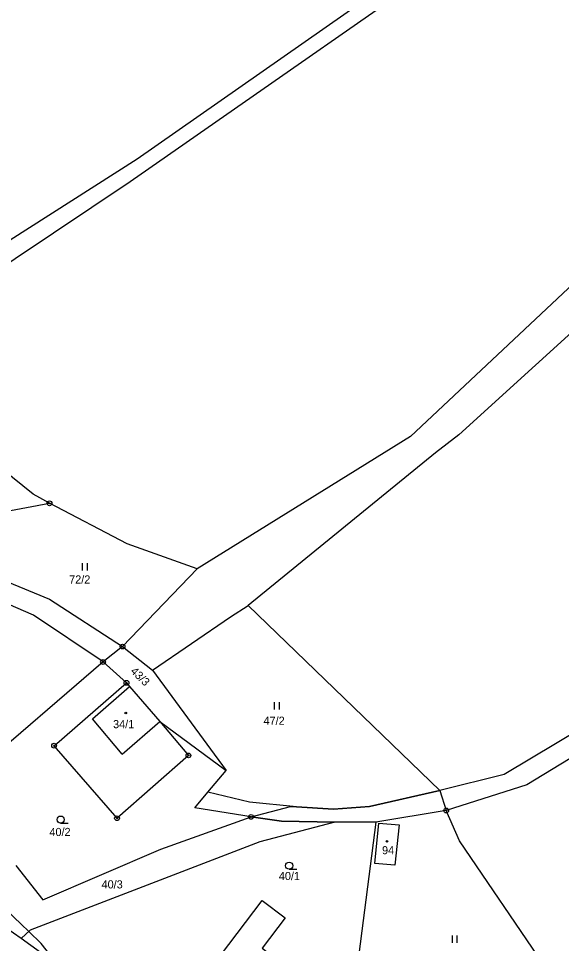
# Model space of a CAD drawing. Extents: x -547623 to -538651, y -1096714 to -1086522.
# Drawn here: x -544383.3 to -544269.6, y -1093367 to -1093173.4 of the extents above; entities that cross this region are included whole.
import ezdxf

# ---------------------------------------------------------------- set-up
doc = ezdxf.new("R2010")
doc.units = 0
for name, color, linetype in [('Vrstva 1', 7, 'Continuous'), ('Vrstva 25', 7, 'Continuous'), ('Vrstva 30', 7, 'Continuous'), ('Vrstva 33', 7, 'Continuous'), ('Vrstva 52', 7, 'Continuous'), ('Vrstva 83', 7, 'Continuous'), ('Vrstva 86', 7, 'Continuous'), ('Vrstva 90', 7, 'Continuous'), ('Vrstva 92', 7, 'Continuous')]:
    doc.layers.add(name, color=color, linetype=linetype)

msp = doc.modelspace()

# ---------------------------------------------------------------- linework, layer by layer
at = {"layer": 'Vrstva 1'}
msp.add_line((-544270.28, -1093375.95), (-544290.96, -1093345.5), dxfattribs=at)
for points in [[(-544280.03, -1093147.98), (-544358.44, -1093202.82)], [(-544278.8, -1093150.99), (-544359.87, -1093207.54)], [(-544358.44, -1093202.82), (-544394.72, -1093225.91)], [(-544359.87, -1093207.54), (-544408.12, -1093239.81)], [(-544264.85, -1093226.71), (-544301.27, -1093260.9)], [(-544259.07, -1093231.36), (-544291.12, -1093260.53)], [(-544301.27, -1093260.9), (-544345.86, -1093288.56)], [(-544291.12, -1093260.53), (-544296.03, -1093264.31)], [(-544380.17, -1093272.94), (-544393.6, -1093262.19)], [(-544296.03, -1093264.31), (-544335.21, -1093296.26)], [(-544376.78, -1093274.85), (-544380.17, -1093272.94)], [(-544399.42, -1093279.07), (-544376.78, -1093274.85)], [(-544360.55, -1093283.34), (-544376.78, -1093274.85)], [(-544402.54, -1093284.32), (-544376.8, -1093294.93)], [(-544345.86, -1093288.56), (-544360.55, -1093283.34)], [(-544380.12, -1093298.26), (-544403.14, -1093288.28)], [(-544345.86, -1093288.56), (-544361.49, -1093304.84)], [(-544376.8, -1093294.93), (-544361.49, -1093304.84)], [(-544338.9, -1093298.62), (-544335.21, -1093296.26)], [(-544295.12, -1093334.97), (-544335.21, -1093296.26)], [(-544365.57, -1093308.07), (-544380.12, -1093298.26)], [(-544355.21, -1093309.78), (-544338.9, -1093298.62)], [(-544361.49, -1093304.84), (-544365.57, -1093308.07)], [(-544361.49, -1093304.84), (-544355.21, -1093309.78)], [(-544365.57, -1093308.07), (-544392.44, -1093331.18)], [(-544360.66, -1093312.44), (-544365.57, -1093308.07)], [(-544355.21, -1093309.78), (-544339.84, -1093330.78)], [(-544375.82, -1093325.59), (-544360.66, -1093312.44)], [(-544360.66, -1093312.44), (-544360.03, -1093313.18)], [(-544360.03, -1093313.18), (-544353.7, -1093320.51)], [(-544253.71, -1093314.94), (-544281.65, -1093331.64)], [(-544353.7, -1093320.51), (-544347.71, -1093327.63)], [(-544353.7, -1093320.51), (-544339.84, -1093330.78)], [(-544257.53, -1093322.02), (-544276.92, -1093333.82)], [(-544362.64, -1093340.78), (-544375.82, -1093325.59)], [(-544347.71, -1093327.63), (-544362.64, -1093340.78)], [(-544343.65, -1093335.33), (-544339.84, -1093330.78)], [(-544281.65, -1093331.64), (-544295.12, -1093334.97)], [(-544346.38, -1093338.58), (-544343.65, -1093335.33)], [(-544334.93, -1093337.42), (-544343.65, -1093335.33)], [(-544295.12, -1093334.97), (-544309.78, -1093338.29)], [(-544276.92, -1093333.82), (-544293.76, -1093339.16)], [(-544334.6, -1093340.5), (-544346.38, -1093338.58)], [(-544325.12, -1093338.42), (-544334.93, -1093337.42)], [(-544317.38, -1093338.87), (-544325.12, -1093338.42)], [(-544309.78, -1093338.29), (-544317.38, -1093338.87)], [(-544293.76, -1093339.16), (-544308.48, -1093341.63)], [(-544290.96, -1093345.5), (-544293.76, -1093339.16)], [(-544353.46, -1093347.24), (-544334.6, -1093340.5)], [(-544334.6, -1093340.5), (-544328.2, -1093341.36)], [(-544317.08, -1093341.62), (-544332.73, -1093345.74)], [(-544328.2, -1093341.36), (-544317.08, -1093341.62)], [(-544308.48, -1093341.63), (-544317.08, -1093341.62)], [(-544308.48, -1093341.63), (-544312.3, -1093371.38)], [(-544308.69, -1093350.22), (-544307.89, -1093341.79)], [(-544307.89, -1093341.79), (-544303.59, -1093342.19)], [(-544303.59, -1093342.19), (-544304.51, -1093350.6)], [(-544332.73, -1093345.74), (-544380.83, -1093364.24)], [(-544378.15, -1093357.88), (-544353.46, -1093347.24)], [(-544383.83, -1093350.69), (-544378.15, -1093357.88)], [(-544304.51, -1093350.6), (-544308.69, -1093350.22)], [(-544342.72, -1093371.8), (-544332.25, -1093357.98), (-544327.45, -1093361.62), (-544332.3, -1093367.95), (-544325.13, -1093373.39), (-544325.91, -1093374.48)], [(-544382.69, -1093365.95), (-544389.17, -1093361.48)], [(-544380.83, -1093364.24), (-544382.69, -1093365.95)], [(-544371.85, -1093373.87), (-544382.69, -1093365.95)]]:
    msp.add_lwpolyline(points, dxfattribs=at)
at = {"layer": 'Vrstva 25'}
for p, q in [((-544369.85, -1093288.89), (-544369.85, -1093287.39)), ((-544368.85, -1093288.89), (-544368.85, -1093287.39)), ((-544329.66, -1093317.99), (-544329.66, -1093316.49)), ((-544328.66, -1093317.99), (-544328.66, -1093316.49)), ((-544374.44, -1093341.82), (-544372.84, -1093341.82)), ((-544326.62, -1093351.46), (-544325.02, -1093351.46)), ((-544292.48, -1093366.85), (-544292.48, -1093365.35)), ((-544291.48, -1093366.85), (-544291.48, -1093365.35))]:
    msp.add_line(p, q, dxfattribs=at)
for centre, radius in [((-544360.82, -1093318.75), 0.175), ((-544374.44, -1093341.07), 0.75), ((-544306.14, -1093345.62), 0.175), ((-544326.62, -1093350.71), 0.75)]:
    msp.add_circle(centre, radius, dxfattribs=at)
at = {"layer": 'Vrstva 30'}
msp.add_lwpolyline([(-544295.12, -1093334.97), (-544293.76, -1093339.16), (-544308.48, -1093341.63), (-544317.08, -1093341.62), (-544328.2, -1093341.36), (-544334.6, -1093340.5), (-544326.38, -1093338.29), (-544325.12, -1093338.42), (-544317.38, -1093338.87), (-544309.78, -1093338.29), (-544295.12, -1093334.97)], dxfattribs=at)
at = {"layer": 'Vrstva 33'}
for points in [[(-544367.81, -1093320), (-544360.03, -1093313.18)], [(-544361.57, -1093327.37), (-544367.81, -1093320)], [(-544361.57, -1093327.37), (-544353.7, -1093320.51)]]:
    msp.add_lwpolyline(points, dxfattribs=at)
at = {"layer": 'Vrstva 52'}
msp.add_lwpolyline([(-544316.75, -1093492.2), (-544317.99, -1093485.92), (-544324.5, -1093453), (-544328.21, -1093446.09), (-544342.58, -1093419.32), (-544344.57, -1093415.62), (-544353.5, -1093399), (-544357.42, -1093393.98), (-544374.84, -1093371.69), (-544378.5, -1093367), (-544381.12, -1093364.5), (-544387.61, -1093358.32), (-544407.19, -1093339.65), (-544419.96, -1093327.47), (-544441.99, -1093306.47), (-544443, -1093305.5), (-544448.53, -1093301.98), (-544453.75, -1093298.65), (-544460.56, -1093294.31), (-544479.26, -1093282.39), (-544481.1, -1093281.22), (-544488.5, -1093276.5), (-544493.29, -1093274.75), (-544509, -1093269)], dxfattribs=at)
at = {"layer": 'Vrstva 83'}
for centre, radius in [((-544376.78, -1093274.85), 0.5), ((-544376.78, -1093274.85), 0.1), ((-544361.49, -1093304.84), 0.5), ((-544361.49, -1093304.84), 0.1), ((-544365.57, -1093308.07), 0.5), ((-544365.57, -1093308.07), 0.1), ((-544360.66, -1093312.44), 0.5), ((-544360.66, -1093312.44), 0.1), ((-544375.82, -1093325.59), 0.5), ((-544375.82, -1093325.59), 0.1), ((-544347.71, -1093327.63), 0.5), ((-544347.71, -1093327.63), 0.1), ((-544293.76, -1093339.16), 0.5), ((-544293.76, -1093339.16), 0.1), ((-544362.64, -1093340.78), 0.5), ((-544362.64, -1093340.78), 0.1), ((-544334.6, -1093340.5), 0.5), ((-544334.6, -1093340.5), 0.1)]:
    msp.add_circle(centre, radius, dxfattribs=at)
at = {"layer": 'Vrstva 90'}
for points in [[(-544367.81, -1093320), (-544360.03, -1093313.18)], [(-544360.03, -1093313.18), (-544353.7, -1093320.51)], [(-544361.57, -1093327.37), (-544367.81, -1093320)], [(-544361.57, -1093327.37), (-544353.7, -1093320.51)], [(-544308.69, -1093350.22), (-544307.89, -1093341.79)], [(-544307.89, -1093341.79), (-544303.59, -1093342.19)], [(-544303.59, -1093342.19), (-544304.51, -1093350.6)], [(-544304.51, -1093350.6), (-544308.69, -1093350.22)], [(-544342.72, -1093371.8), (-544332.25, -1093357.98), (-544327.45, -1093361.62), (-544332.3, -1093367.95), (-544325.13, -1093373.39), (-544325.91, -1093374.48)]]:
    msp.add_lwpolyline(points, dxfattribs=at)

# ---------------------------------------------------------------- texts
at = {"layer": 'Vrstva 86'}
for s, p in [('72/2', (-544372.66, -1093291.64)), ('47/2', (-544331.99, -1093321.21)), ('40/2', (-544376.79, -1093344.5)), ('40/1', (-544328.78, -1093353.72)), ('40/3', (-544365.88, -1093355.47))]:
    msp.add_text(s, height=1.7, dxfattribs=at).set_placement(p)
msp.add_text('43/3', height=1.7, rotation=315.3684, dxfattribs=at).set_placement((-544359.96, -1093310.14))
at = {"layer": 'Vrstva 92'}
for s, p in [('34/1', (-544363.47, -1093321.93)), ('94', (-544307.19, -1093348.32))]:
    msp.add_text(s, height=1.7, dxfattribs=at).set_placement(p)

doc.saveas('drawing.dxf')
